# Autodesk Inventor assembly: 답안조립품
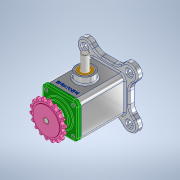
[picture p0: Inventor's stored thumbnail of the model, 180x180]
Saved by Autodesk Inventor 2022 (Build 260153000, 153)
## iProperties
Created: 2022-05
Part Number: 답안조립품
Document SubType Name: Assembly
Designer: Admin
Author: Admin
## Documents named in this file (11)
- C:\Users\Admin\Desktop\720509V1008\답안조립품.iam
- C:\Users\Admin\Desktop\720509V1008\본체.ipt
- C:\Users\Admin\Desktop\720509V1008\커버.ipt
- C:\Users\Admin\Desktop\720509V1008\베어링 6203.ipt
- C:\Users\Admin\Desktop\720509V1008\편심축.ipt
- C:\Users\Admin\Desktop\720509V1008\오일 실.ipt
- C:\Users\Admin\Desktop\720509V1008\부시.ipt
- C:\Users\Admin\Desktop\720509V1008\슬라이더.ipt
- C:\Users\Admin\Desktop\720509V1008\키 4 x 4 x 14.ipt
- C:\Users\Admin\Desktop\720509V1008\스프로킷.ipt
- C:\Users\Admin\Desktop\720509V1008\볼트 M4.ipt
